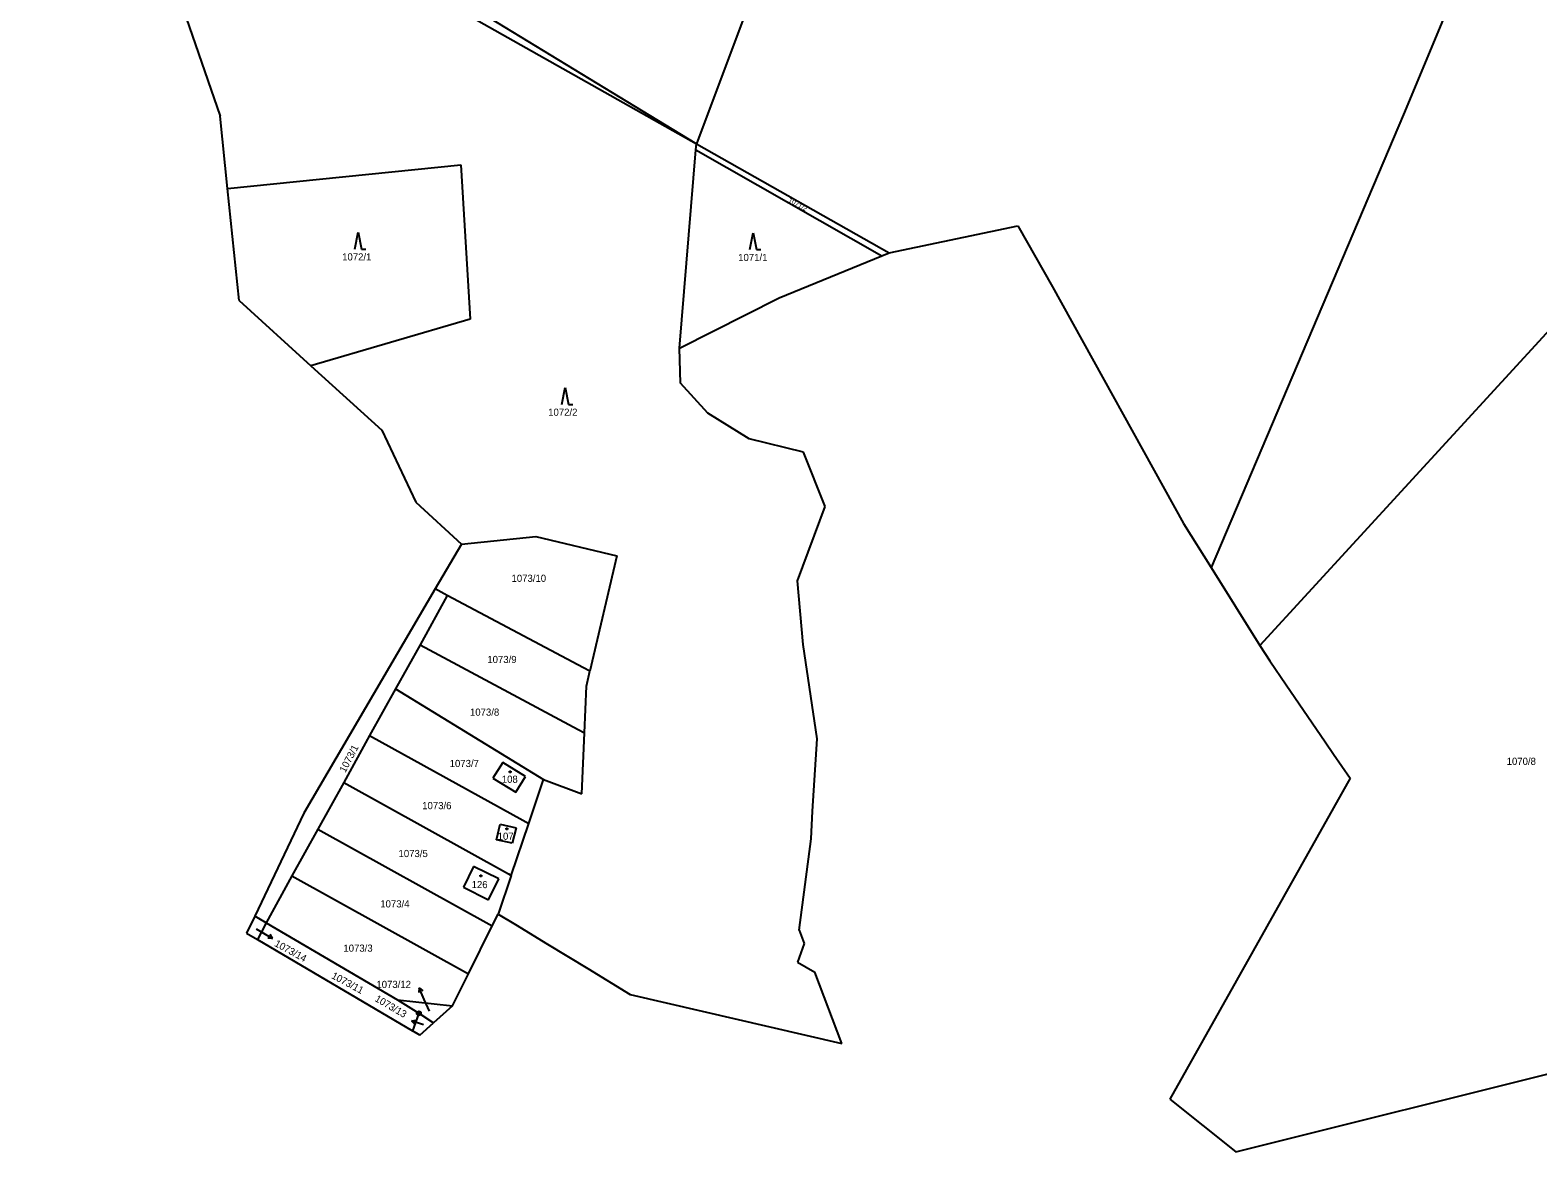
# Model space of a CAD drawing. Extents: x -794142 to -791199, y -1109267 to -1105626.
# Drawn here: x -792501.1 to -792142.9, y -1109133.1 to -1108866.7 of the extents above; entities that cross this region are included whole.
import ezdxf

# ---------------------------------------------------------------- set-up
doc = ezdxf.new("R2010")
doc.units = 0
for name, color, linetype in [('Komunikace', 7, 'Continuous'), ('Vrstva 1', 7, 'Continuous'), ('Vrstva 14', 7, 'Continuous'), ('Vrstva 15', 7, 'Continuous'), ('Vrstva 16', 7, 'Continuous'), ('Vrstva 23', 7, 'Continuous'), ('Vrstva 25', 7, 'Continuous'), ('Vrstva 28', 7, 'Continuous'), ('Vrstva 4', 7, 'Continuous')]:
    doc.layers.add(name, color=color, linetype=linetype)

msp = doc.modelspace()

# ---------------------------------------------------------------- linework, layer by layer
at = {"layer": 'Komunikace'}
for p, q in [((-792447.43, -1109080.12), (-792446.11, -1109080.89)), ((-792406.25, -1109099.71), (-792407.51, -1109096.91)), ((-792407.68, -1109102.94), (-792407.69, -1109102.94))]:
    msp.add_line(p, q, dxfattribs=at)
at = {"layer": 'Vrstva 1'}
for p, q in [((-792275.03, -1108712.47), (-792342.83, -1108893.7)), ((-792144.15, -1108813.19), (-792174.82, -1108886.71)), ((-792455.43, -1108830.13), (-792342.83, -1108893.7)), ((-792393.83, -1108862.6), (-792342.83, -1108893.7)), ((-792174.82, -1108886.71), (-792220.52, -1108994.32)), ((-792342.94, -1108895.06), (-792342.83, -1108893.7)), ((-792342.83, -1108893.7), (-792297.03, -1108919.55)), ((-792346.85, -1108942.21), (-792342.94, -1108895.06)), ((-792342.94, -1108895.06), (-792298.77, -1108920.26)), ((-792454.22, -1108904.32), (-792398.79, -1108898.63)), ((-792398.79, -1108898.63), (-792396.63, -1108935.32)), ((-792396.63, -1108935.32), (-792434.42, -1108946.37)), ((-792140.08, -1108937.77), (-792208.94, -1109012.8)), ((-792398.66, -1108988.73), (-792380.96, -1108986.91)), ((-792380.96, -1108986.91), (-792361.74, -1108991.56)), ((-792361.74, -1108991.56), (-792368.14, -1109018.91)), ((-792402.04, -1109000.95), (-792408.51, -1109012.64)), ((-792402.04, -1109000.95), (-792404.9, -1108999.39)), ((-792369.65, -1109018.11), (-792402.04, -1109000.95)), ((-792408.51, -1109012.64), (-792414.33, -1109023.13)), ((-792408.51, -1109012.64), (-792370.94, -1109032.76)), ((-792368.14, -1109018.91), (-792369.65, -1109018.11)), ((-792368.98, -1109022.53), (-792368.14, -1109018.91)), ((-792369.45, -1109033.56), (-792368.98, -1109022.53)), ((-792414.33, -1109023.13), (-792420.48, -1109034.24)), ((-792414.33, -1109023.13), (-792379.17, -1109044.69)), ((-792370.94, -1109032.76), (-792369.45, -1109033.56)), ((-792420.48, -1109034.24), (-792426.64, -1109045.35)), ((-792420.48, -1109034.24), (-792384.12, -1109054.32)), ((-792370.07, -1109048.06), (-792369.45, -1109033.56)), ((-792388.87, -1109040.61), (-792391.17, -1109044.37)), ((-792383.41, -1109043.95), (-792388.87, -1109040.61)), ((-792385.71, -1109047.7), (-792383.41, -1109043.95)), ((-792426.64, -1109045.35), (-792432.79, -1109056.46)), ((-792426.64, -1109045.35), (-792387.47, -1109067.07)), ((-792391.17, -1109044.37), (-792385.71, -1109047.7)), ((-792382.69, -1109055.11), (-792379.17, -1109044.69)), ((-792379.17, -1109044.69), (-792370.07, -1109048.06)), ((-792384.12, -1109054.32), (-792382.69, -1109055.11)), ((-792432.79, -1109056.46), (-792438.95, -1109067.57)), ((-792432.79, -1109056.46), (-792391.34, -1109079.44)), ((-792390.3, -1109058.97), (-792389.45, -1109055.29)), ((-792389.45, -1109055.29), (-792385.69, -1109056.14)), ((-792386.82, -1109067.43), (-792382.69, -1109055.11)), ((-792385.69, -1109056.14), (-792386.62, -1109059.82)), ((-792386.62, -1109059.82), (-792390.3, -1109058.97)), ((-792395.81, -1109065.36), (-792398.21, -1109070.27)), ((-792389.82, -1109068.29), (-792395.81, -1109065.36)), ((-792438.95, -1109067.57), (-792445.1, -1109078.68)), ((-792438.95, -1109067.57), (-792397.02, -1109090.8)), ((-792392.24, -1109073.21), (-792389.82, -1109068.29)), ((-792386.82, -1109067.43), (-792389.93, -1109076.62)), ((-792387.47, -1109067.07), (-792386.82, -1109067.43)), ((-792398.21, -1109070.27), (-792392.24, -1109073.21)), ((-792445.1, -1109078.68), (-792447.77, -1109077.11)), ((-792445.1, -1109078.68), (-792447.09, -1109082.69)), ((-792445.1, -1109078.68), (-792413.86, -1109097.02)), ((-792413.86, -1109097.02), (-792408.78, -1109100.2)), ((-792413.86, -1109097.02), (-792400.81, -1109098.39)), ((-792408.78, -1109100.2), (-792410.28, -1109104.39)), ((-792408.78, -1109100.2), (-792405.31, -1109102.47))]:
    msp.add_line(p, q, dxfattribs=at)
at = {"layer": 'Vrstva 16'}
for p, q in [((-792446.11, -1109080.89), (-792443.521, -1109082.406)), ((-792443.521, -1109082.406), (-792444.636, -1109082.332)), ((-792443.521, -1109082.406), (-792444.131, -1109081.469)), ((-792408.745, -1109094.176), (-792408.789, -1109095.293)), ((-792407.51, -1109096.91), (-792408.745, -1109094.176)), ((-792408.745, -1109094.176), (-792407.878, -1109094.881)), ((-792410.54, -1109102.003), (-792409.433, -1109101.84)), ((-792407.69, -1109102.94), (-792410.54, -1109102.003)), ((-792410.54, -1109102.003), (-792409.746, -1109102.79))]:
    msp.add_line(p, q, dxfattribs=at)
at = {"layer": 'Vrstva 23'}
for p, q in [((-792424.01, -1108918.68), (-792423.21, -1108914.68)), ((-792423.21, -1108914.68), (-792422.41, -1108918.68)), ((-792330.14, -1108918.81), (-792329.34, -1108914.81)), ((-792329.34, -1108914.81), (-792328.54, -1108918.81)), ((-792422.41, -1108918.68), (-792421.41, -1108918.68)), ((-792328.54, -1108918.81), (-792327.54, -1108918.81)), ((-792374.83, -1108955.57), (-792374.03, -1108951.57)), ((-792374.03, -1108951.57), (-792373.23, -1108955.57)), ((-792373.23, -1108955.57), (-792372.23, -1108955.57))]:
    msp.add_line(p, q, dxfattribs=at)
at = {"layer": 'Vrstva 25'}
for p, q in [((-792387.21, -1109042.69), (-792386.91, -1109042.69)), ((-792387.21, -1109042.99), (-792387.21, -1109042.69)), ((-792386.91, -1109042.99), (-792387.21, -1109042.99)), ((-792386.91, -1109042.69), (-792386.91, -1109042.99)), ((-792388.06, -1109056.21), (-792387.76, -1109056.21)), ((-792388.06, -1109056.51), (-792388.06, -1109056.21)), ((-792387.76, -1109056.51), (-792388.06, -1109056.51)), ((-792387.76, -1109056.21), (-792387.76, -1109056.51)), ((-792394.2, -1109067.41), (-792393.9, -1109067.41)), ((-792394.2, -1109067.71), (-792394.2, -1109067.41)), ((-792393.9, -1109067.71), (-792394.2, -1109067.71)), ((-792393.9, -1109067.41), (-792393.9, -1109067.71))]:
    msp.add_line(p, q, dxfattribs=at)
at = {"layer": 'Vrstva 28'}
for radius in [0.5, 0.01]:
    msp.add_circle((-792408.78, -1109100.2), radius, dxfattribs=at)
at = {"layer": 'Vrstva 4'}
for p, q in [((-792454.22, -1108904.32), (-792456.02, -1108887.07)), ((-792451.45, -1108930.9), (-792454.22, -1108904.32)), ((-792297.03, -1108919.55), (-792266.44, -1108913.19)), ((-792266.44, -1108913.19), (-792258.2, -1108927.65)), ((-792323.14, -1108930.24), (-792298.77, -1108920.26)), ((-792298.77, -1108920.26), (-792297.03, -1108919.55)), ((-792258.2, -1108927.65), (-792227.07, -1108983.86)), ((-792451.45, -1108930.9), (-792434.42, -1108946.37)), ((-792346.85, -1108942.21), (-792323.14, -1108930.24)), ((-792346.62, -1108950.49), (-792346.85, -1108942.21)), ((-792434.42, -1108946.37), (-792417.57, -1108961.68)), ((-792340.11, -1108957.68), (-792346.62, -1108950.49)), ((-792330.34, -1108963.74), (-792340.11, -1108957.68)), ((-792417.57, -1108961.68), (-792409.53, -1108978.79)), ((-792317.38, -1108966.91), (-792330.34, -1108963.74)), ((-792312.26, -1108979.8), (-792317.38, -1108966.91)), ((-792409.53, -1108978.79), (-792398.66, -1108988.73)), ((-792318.8, -1108997.47), (-792312.26, -1108979.8)), ((-792227.07, -1108983.86), (-792220.52, -1108994.32)), ((-792398.66, -1108988.73), (-792404.9, -1108999.39)), ((-792317.45, -1109012.56), (-792318.8, -1108997.47)), ((-792220.52, -1108994.32), (-792208.94, -1109012.8)), ((-792404.9, -1108999.39), (-792436.11, -1109052.69)), ((-792314.17, -1109034.98), (-792317.45, -1109012.56)), ((-792208.94, -1109012.8), (-792206.63, -1109016.5)), ((-792206.63, -1109016.5), (-792202.75, -1109022.16)), ((-792202.75, -1109022.16), (-792193.47, -1109035.7)), ((-792315.25, -1109052.2), (-792314.17, -1109034.98)), ((-792193.47, -1109035.7), (-792191.44, -1109038.66)), ((-792191.44, -1109038.66), (-792187.53, -1109044.37)), ((-792187.53, -1109044.37), (-792230.38, -1109120.61)), ((-792436.11, -1109052.69), (-792447.77, -1109077.11)), ((-792315.59, -1109058.72), (-792315.25, -1109052.2)), ((-792318.42, -1109080.47), (-792315.59, -1109058.72)), ((-792447.77, -1109077.11), (-792449.7, -1109081.15)), ((-792397.02, -1109090.8), (-792391.34, -1109079.44)), ((-792391.34, -1109079.44), (-792389.93, -1109076.62)), ((-792389.93, -1109076.62), (-792385.83, -1109079.12)), ((-792385.83, -1109079.12), (-792378.24, -1109083.75)), ((-792449.7, -1109081.15), (-792447.09, -1109082.69)), ((-792447.09, -1109082.69), (-792410.28, -1109104.39)), ((-792317.23, -1109083.65), (-792318.83, -1109088.07)), ((-792318.42, -1109080.47), (-792317.23, -1109083.65)), ((-792378.24, -1109083.75), (-792368.66, -1109089.58)), ((-792400.81, -1109098.39), (-792397.02, -1109090.8)), ((-792368.66, -1109089.58), (-792358.59, -1109095.72)), ((-792318.83, -1109088.07), (-792314.7, -1109090.39)), ((-792308.32, -1109107.39), (-792314.7, -1109090.39)), ((-792358.59, -1109095.72), (-792308.32, -1109107.39)), ((-792400.81, -1109098.39), (-792405.31, -1109102.47)), ((-792408.56, -1109105.41), (-792410.28, -1109104.39)), ((-792408.56, -1109105.41), (-792405.31, -1109102.47)), ((-792214.64, -1109133.1), (-792120.39, -1109109.5)), ((-792230.38, -1109120.61), (-792214.64, -1109133.1))]:
    msp.add_line(p, q, dxfattribs=at)
msp.add_lwpolyline([(-792501.14, -1108809.95), (-792486.2, -1108837.44), (-792473.34, -1108852.15), (-792464.09, -1108863.71), (-792456.02, -1108887.07)], dxfattribs=at)

# ---------------------------------------------------------------- texts
at = {"layer": 'Vrstva 14'}
for s, height, rotation, p in [('1071/2', 1.14, 331.35516, (-792321.137, -1108907.427)), ('1073/1', 1.7, 62.53119, (-792426.253, -1109043.161)), ('1073/11', 1.7, 331.88463, (-792429.714, -1109091.776))]:
    msp.add_text(s, height=height, rotation=rotation, dxfattribs=at).set_placement(p)
for s, height, p in [('1072/1', 1.7, (-792427.012, -1108921.38)), ('1071/1', 1.7, (-792332.915, -1108921.51)), ('1072/2', 1.7, (-792378.058, -1108958.27)), ('1073/10', 1.7, (-792386.771, -1108997.72)), ('1073/9', 1.7, (-792392.519, -1109017)), ('1073/8', 1.7, (-792396.639, -1109029.51)), ('1073/7', 1.7, (-792401.465, -1109041.7)), ('1070/8', 1.7, (-792150.328, -1109041.19)), ('1073/6', 1.7, (-792407.989, -1109051.71)), ('1073/5', 1.7, (-792413.615, -1109063.09)), ('1073/4', 1.7, (-792417.955, -1109075.05)), ('1073/14', 0.1, (-792447.698, -1109080.12)), ('1073/3', 1.7, (-792426.719, -1109085.57)), ('1073/12', 0.1, (-792406.518, -1109099.71)), ('1073/13', 0.1, (-792407.949, -1109102.94))]:
    msp.add_text(s, height=height, dxfattribs=at).set_placement(p)
at = {"layer": 'Vrstva 15'}
for s, p in [('108', (-792389.079, -1109045.45)), ('107', (-792390.056, -1109058.98)), ('126', (-792396.25, -1109070.47))]:
    msp.add_text(s, height=1.7, dxfattribs=at).set_placement(p)
at = {"layer": 'Vrstva 16'}
for s, rotation, p in [('1073/14', 331.29612, (-792443.256, -1109084.121)), ('1073/13', 329.74668, (-792419.406, -1109097.192))]:
    msp.add_text(s, height=1.7, rotation=rotation, dxfattribs=at).set_placement(p)
msp.add_text('1073/12', height=1.7, dxfattribs=at).set_placement((-792418.874, -1109094.18))

doc.saveas('drawing.dxf')
